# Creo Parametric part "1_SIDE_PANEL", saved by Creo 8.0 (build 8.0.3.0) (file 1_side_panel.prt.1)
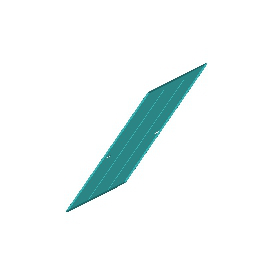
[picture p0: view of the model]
Units: millimeter Newton Second (mmNs); MM, TONNE, SECS

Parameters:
  SMT_DFLT_BEND_REL_LENGTH_TYPE = "Through All"

Other parameters: D17, D12, D16, D7, D13, D8, SMT_THICKNESS, SMT_PART_BEND_ALLOWANCE_FACTOR, SMT_DFLT_BEND_RADIUS, SMT_DFLT_BEND_ANGLE, SMT_DFLT_CRNR_REL_WIDTH, SMT_DFLT_CRNR_REL_DEPTH, SMT_DFLT_BEND_REL_WIDTH, SMT_DFLT_BEND_REL_DEPTH, SMT_DFLT_BEND_REL_LENGTH, SMT_DFLT_BEND_REL_ANGLE, SMT_GAP, SMT_DFLT_EDGE_TREA_WIDTH, SMT_DFLT_MITER_CUT_WIDTH, SMT_DFLT_MITER_CUT_OFFSET

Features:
  1. datum plane "DTM1"
  2. datum plane "DTM2"
  3. datum plane "DTM3"
  4. coordinate system
  5. datum plane "DTM12"
  6. datum plane "DTM13"
  7. datum plane "DTM14"
  8. protrusion
  9. cut
  10. cut
  11. round
  12. round
  13. cut
  14. datum plane "DTM4"
  15. datum plane "DTM5"
  16. datum plane "DTM6"
  17. datum plane "DTM7"
  18. datum plane "DTM8"
  19. datum plane "DTM9"
  20. datum plane "DTM10"
  21. datum plane "DTM11"
  22. cut
  23. cut
  24. cut

Other named items: HEM_1960, HEM_2026, CS0

Layers: 0_ALL_AXIS, 0_ALL_CSYS, 0_ALL_CURVES, 0_ALL_PLANES, 0_ALL_POINTS, 0_ALL_SURFS, 0_SIDE_PANEL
